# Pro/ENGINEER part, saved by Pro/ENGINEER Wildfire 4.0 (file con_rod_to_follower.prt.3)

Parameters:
  METRIC = "NO"

Other parameters: PITCH, DRILL_POINT_ANGLE, DRILL_DEPTH, DRILL_DIAMETER, THREAD_DIAMETER, THREADS_PER_INCH, THREAD_DEPTH, THREAD_LENGTH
